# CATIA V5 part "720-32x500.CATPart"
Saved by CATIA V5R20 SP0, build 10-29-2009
Part number: 720-32x500
Definition: NONE
Nomenclature: 720-32x500
Source: Unknown
Description: 720-32x500
Bounding box of the stored display mesh (mm): x 0 to 500, y -16 to 16, z -16 to 16
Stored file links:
  C:\Users\Utente\Desktop\IO LAVORO\3D X SITO CF\X SITO\720\720-32x500.CATPart
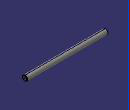
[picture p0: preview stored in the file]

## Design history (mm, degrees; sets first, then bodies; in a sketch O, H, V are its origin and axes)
Body1 "720-32x500" (main body)
  Solid1: solid without history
